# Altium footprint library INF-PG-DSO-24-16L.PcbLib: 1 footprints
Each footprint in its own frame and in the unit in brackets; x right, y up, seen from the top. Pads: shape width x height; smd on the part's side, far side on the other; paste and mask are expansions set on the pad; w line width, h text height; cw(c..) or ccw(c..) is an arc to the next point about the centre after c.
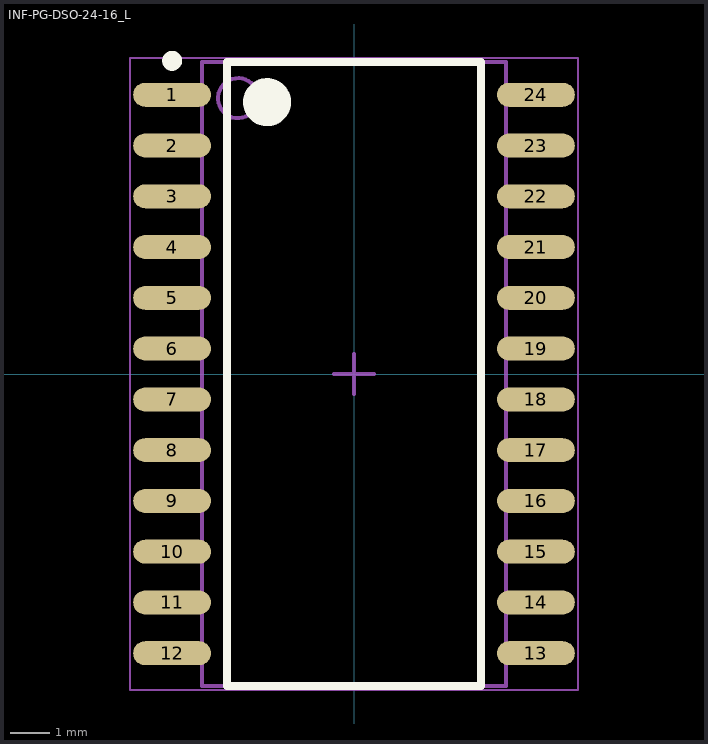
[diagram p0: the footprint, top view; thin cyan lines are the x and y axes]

## INF-PG-DSO-24-16_L [mm] "SOP, 24-Leads, Body 15.4x7.5mm, Pitch 1.27mm, IPC High Density"
height 2.65
pads (24):
  oval 1.95x0.6 smd: 1(-4.55,6.985) 2(-4.55,5.715) 3(-4.55,4.445) 4(-4.55,3.175) 5(-4.55,1.905) 6(-4.55,0.635) 7(-4.55,-0.635) 8(-4.55,-1.905) 9(-4.55,-3.175) 10(-4.55,-4.445) 11(-4.55,-5.715) 12(-4.55,-6.985) 13(4.55,-6.985) 14(4.55,-5.715) 15(4.55,-4.445) 16(4.55,-3.175) 17(4.55,-1.905) 18(4.55,-0.635) 19(4.55,0.635) 20(4.55,1.905) 21(4.55,3.175) 22(4.55,4.445) 23(4.55,5.715) 24(4.55,6.985)
Top Overlay:
  circle w0.6: c-2.175,6.8 r0.3
  circle w0.25: c-4.55,7.835 r0.125
  lines w0.2: -3.175,-7.8 3.175,-7.8 3.175,7.8 -3.175,7.8 -3.175,-7.8
Mechanical 13:
  circle w0.1: c-2.9,6.9 r0.5
  lines w0.1: -3.8,-7.8 3.8,-7.8 3.8,7.8 -3.8,7.8 -3.8,-7.8
Mechanical 15:
  lines w0.05: -5.6,-7.9 5.6,-7.9 5.6,7.9 -5.6,7.9 -5.6,-7.9
  lines w0.1: -0.5,0 0.5,0 ; 0,-0.5 0,0.5
3D body: height 2.65, standoff 0.1, extent -3.8,-7.8 3.8,7.8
